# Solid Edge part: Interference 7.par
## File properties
Last saved by: Lee
Revision: 59
Accuracy: 0.990
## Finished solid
Body 1: solid body, 4 faces, 4 edges, 0 vertices.
  Faces by surface: cylinder 4
  Edges by curve: intersection 4
Bounding box of the edges (mm): 101.889 x 219.073 x 304.967, from (-809.4284, 166.463, 214.5108) to (-707.5393, 385.5361, 519.4775).
Cylindrical faces by radius (mm): R91 x1, R109.5375 x1, R850 x1, R875.4 x1
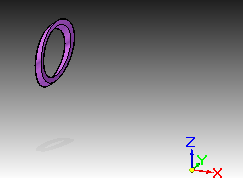
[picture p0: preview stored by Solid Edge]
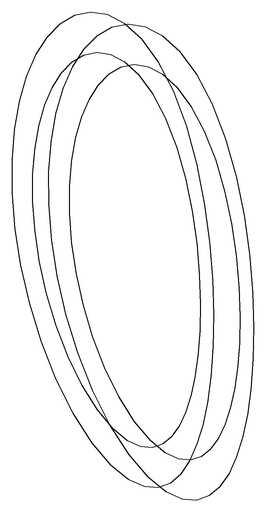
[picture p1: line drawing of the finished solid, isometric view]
